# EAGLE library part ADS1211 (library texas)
24-Bit ANALOG-TO-DIGITAL CONVERTER Source: http://focus.ti.com/lit/ds/symlink/ads1210.pdf
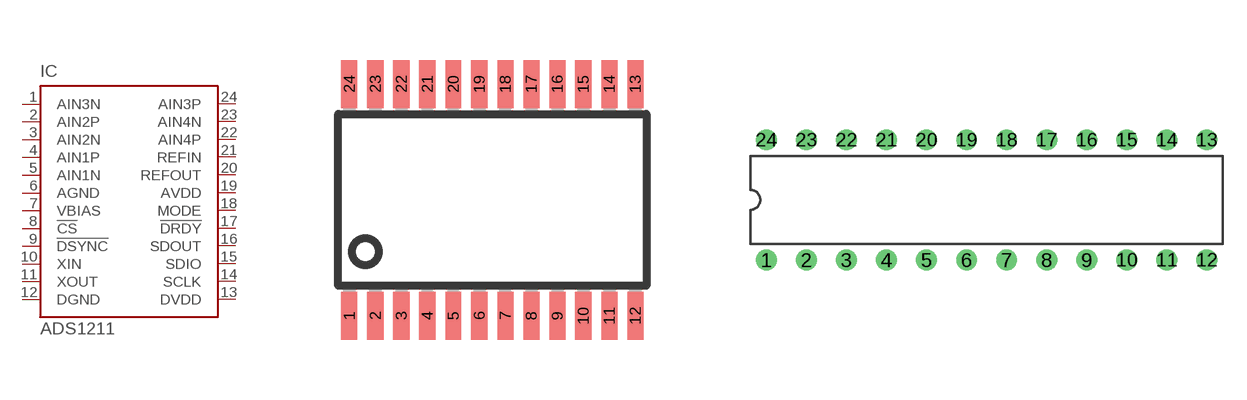
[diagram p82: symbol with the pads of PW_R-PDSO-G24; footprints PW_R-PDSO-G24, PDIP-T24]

Designator prefix IC

## ADS1211U (MF: TEXAS INSTRUMENTS; MPN: ADS1211U; OC_FARNELL: 9324070; OC_NEWARK: 35C1513)  [PW_R-PDSO-G24]
1  AIN3N  in
2  AIN2P  in
3  AIN2N  in
4  AIN1P  in
5  AIN1N  in
6  AGND  pwr
7  VBIAS  in
8  !CS  in
9  !DSYNC  in
10  XIN  in
11  XOUT  out
12  DGND  pwr
13  DVDD  pwr
14  SCLK
15  SDIO
16  SDOUT  out
17  !DRDY  in
18  MODE  in
19  AVDD  pwr
20  REFOUT  out
21  REFIN  in
22  AIN4P  in
23  AIN4N  in
24  AIN3P  in

## ADS1211P (MF: TEXAS INSTRUMENTS; MPN: ADS1211P; OC_FARNELL: 1219430; OC_NEWARK: 96K2329)  [PDIP-T24]
Pads as for PW_R-PDSO-G24

## Footprint PW_R-PDSO-G24 (pad centres in mm)
PLASTIC SMALL-OUTLINE PACKAGE SO 24 JEDEC MO-153, PW Type Source: www.ti.com/.. slvs087l.pdf
smd 0.4 x 1.2: 1 -3.575,-2.9; 2 -2.925,-2.9; 3 -2.275,-2.9; 4 -1.625,-2.9; 5 -0.975,-2.9; 6 -0.325,-2.9; 7 0.325,-2.9; 8 0.975,-2.9; 9 1.625,-2.9; 10 2.275,-2.9; 11 2.925,-2.9; 12 3.575,-2.9; 13 3.575,2.9; 14 2.925,2.9; 15 2.275,2.9; 16 1.625,2.9; 17 0.975,2.9; 18 0.325,2.9; 19 -0.325,2.9; 20 -0.975,2.9; 21 -1.625,2.9; 22 -2.275,2.9; 23 -2.925,2.9; 24 -3.575,2.9

## Footprint PDIP-T24 (pad centres in mm)
NT (R-PDIP-T24) PLASTIC DUAL-IN-LINE PACKAGE Source: http://focus.ti.com/lit/ml/mpdi004a/mpdi004a.pdf
drill 0.813 pad 1.2 round: 1 -13.97,-3.81; 2 -11.43,-3.81; 3 -8.89,-3.81; 4 -6.35,-3.81; 5 -3.81,-3.81; 6 -1.27,-3.81; 7 1.27,-3.81; 8 3.81,-3.81; 9 6.35,-3.81; 10 8.89,-3.81; 11 11.43,-3.81; 12 13.97,-3.81; 13 13.97,3.81; 14 11.43,3.81; 15 8.89,3.81; 16 6.35,3.81; 17 3.81,3.81; 18 1.27,3.81; 19 -1.27,3.81; 20 -3.81,3.81; 21 -6.35,3.81; 22 -8.89,3.81; 23 -11.43,3.81; 24 -13.97,3.81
